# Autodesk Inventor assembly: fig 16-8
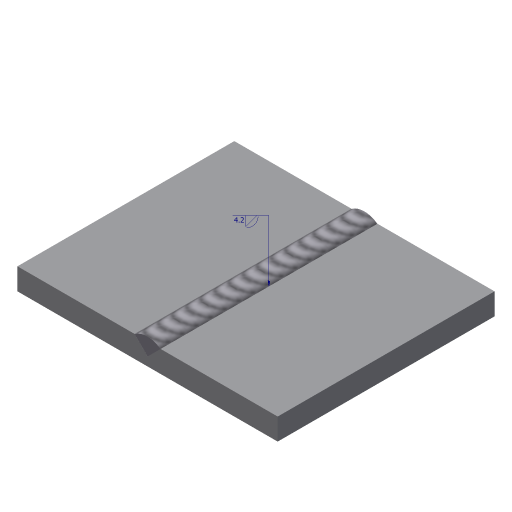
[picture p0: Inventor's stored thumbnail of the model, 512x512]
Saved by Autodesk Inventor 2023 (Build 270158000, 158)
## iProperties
Created: 2004-07
Part Number: fig 16-8
Document SubType Name: Weldment
Designer: CADCIM Technologies
Manufacturer: Standard
Standards Organization: Custom
Author: CADCIM Technologies
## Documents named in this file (2)
- D:\PROJECTS\Project 2022\Autodesk Inventor For Professional 2023\RESOURCES INVENTOR 2023\RESOURCES INVENTOR 2023\Inventor_2023_Part\Inventor_2023_Part\c16_Inv_2023_prt\fig 16-8\fig 16-8.iam
- D:\PROJECTS\Project 2022\Autodesk Inventor For Professional 2023\RESOURCES INVENTOR 2023\RESOURCES INVENTOR 2023\Inventor_2023_Part\Inventor_2023_Part\c16_Inv_2023_prt\fig 16-8\Plate.ipt
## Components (2 placed, 1 different names)
1. Plate:1 — Mate:1, Flush:1, Flush:2
2. Plate:2 — Mate:1, Flush:1, Flush:2
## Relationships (3: Flush 2, Mate 1)
- Mate:1: Plate:1 ↔ Plate:2
- Flush:1: Plate:1 ↔ Plate:2
- Flush:2: Plate:1 ↔ Plate:2
